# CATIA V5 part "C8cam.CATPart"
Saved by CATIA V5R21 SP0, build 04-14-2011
Part number: C8cam
Bounding box of the stored display mesh (mm): x -19.048 to 19.048, y -50.8 to 0, z -18.859 to 46.837
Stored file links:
  C:\Users\User\Desktop\B.D.M.A\Chapter8\C8cam.CATPart
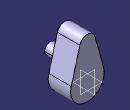
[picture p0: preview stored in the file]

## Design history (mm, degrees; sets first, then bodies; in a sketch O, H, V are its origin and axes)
Body1 (main body)
  Sketch1 on zx-plane, origin (0, 0, 0), H (-1, 0, 0), V (0, 0, 1)
    arc A1 centre (0, 0) radius 19.05 from (-18.3602, 5.08) to (18.3602, 5.08) ccw
    arc A2 centre (0, 38.1) radius 8.89 from (8.5681, 40.4707) to (-8.5681, 40.4707) ccw
    point P1 (0, 38.1)
    line L1 (-8.5681, 40.4707) -> (-18.3602, 5.08)
    line L2 (8.5681, 40.4707) -> (18.3602, 5.08)
    radius A1 = 19.05
    radius A2 = 8.89
    distance P1 O = 38.1
    coincidence: P1 V
    tangency: A2 L2, A1 L2, L1 A2, A1 L1
  Pad1: profile Sketch1, direction (0, -1, 0), length 25.4
  Sketch2 on end face of Pad1, origin (0, -25.4, 0), H (1, 0, 0), V (0, 0, 1)
    circle A1 centre (-8.6135, 3.6275) radius 6.35
    radius A1 = 6.35
  Pad2: profile Sketch2, direction (0, -1, 0), length 25.4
